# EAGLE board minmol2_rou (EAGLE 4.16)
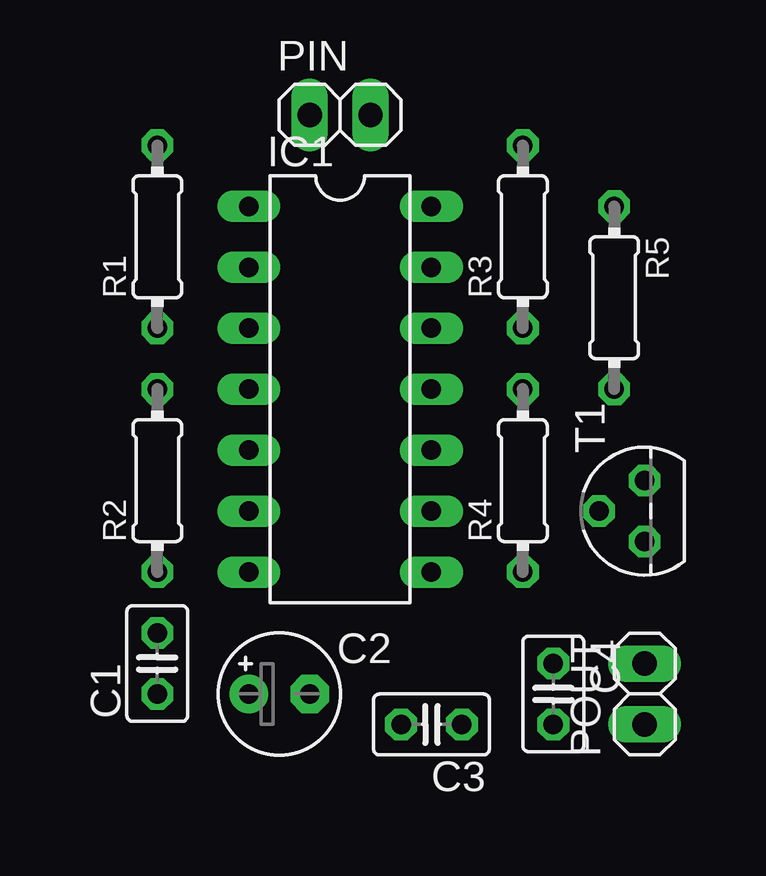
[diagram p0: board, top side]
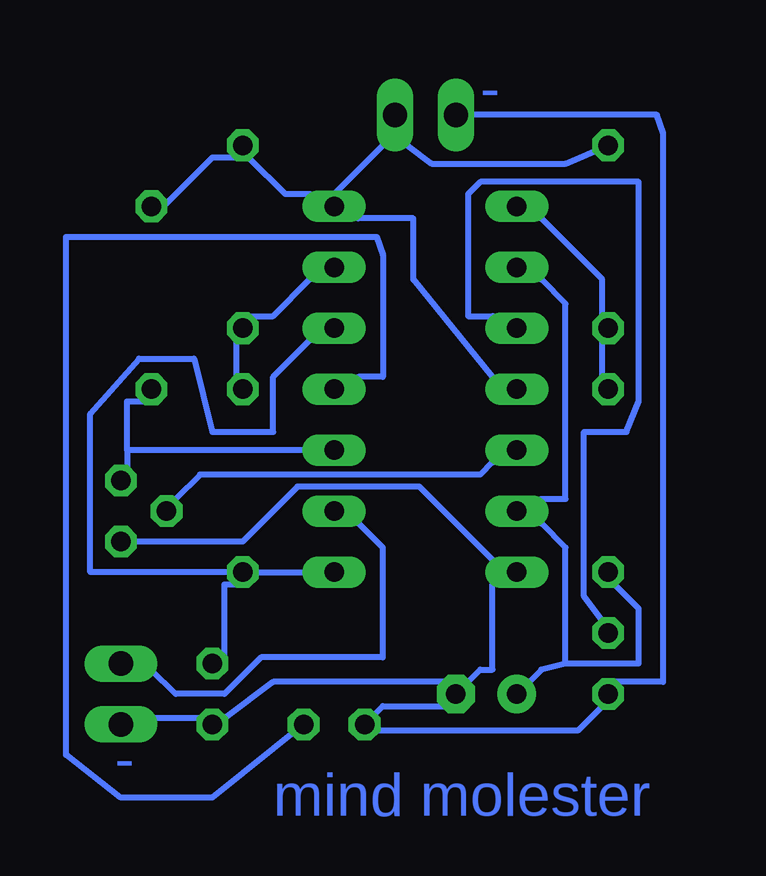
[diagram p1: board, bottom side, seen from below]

No outline drawn. Coordinates in mm, seen from the top.
Copper layers (1*16): Top 0.035mm / dielectric 1.5mm / Bottom 0.035mm
Design rules "default": minimum track width 10mil, minimum drill 24mil, track to track 8mil, track to pad 8mil, pad to pad 8mil, via to via 8mil, smd to smd 8mil, copper to edge 40mil, drill to drill 8mil, minimum pad ring 10mil, minimum via ring 8mil, stop-mask expansion 4mil, vias tented up to drill 0mil, thermal gap 10mil

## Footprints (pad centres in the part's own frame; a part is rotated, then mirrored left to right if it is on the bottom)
C025-025X050 = drill 0.813 octagon: 1 -1.27,0; 2 1.27,0
E2,5-5 = drill 0.813 pad 1.6 round: + -1.27,0 | drill 0.813 pad 1.6 octagon: - 1.27,0
DIL14 = drill 0.813 long: 1 -7.62,-3.81; 2 -5.08,-3.81; 3 -2.54,-3.81; 4 0,-3.81; 5 2.54,-3.81; 6 5.08,-3.81; 7 7.62,-3.81; 8 7.62,3.81; 9 5.08,3.81; 10 2.54,3.81; 11 0,3.81; 12 -2.54,3.81; 13 -5.08,3.81; 14 -7.62,3.81
1X02 = drill 1.016 long: 1 -1.27,0; 2 1.27,0
0204/7 = drill 0.813 octagon: 1 -3.81,0; 2 3.81,0
TO92 = drill 0.813 octagon: 1 -1.27,0; 2 0,1.905; 3 1.27,0

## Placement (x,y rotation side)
C1  100n  [C025-025X050]  21.59,6.35 90 top
C2  20u  [E2,5-5]  26.67,5.08 0 top
C3  100n  [C025-025X050]  33.02,3.81 180 top
C4  1n  [C025-025X050]  38.1,5.08 270 top
IC1  ICL7556  [DIL14]  29.21,17.78 270 top
PIN  [1X02]  29.21,29.21 0 top
POUT  [1X02]  41.91,5.08 90 top
R1  10M  [0204/7]  21.59,24.13 90 top
R2  20k  [0204/7]  21.59,13.97 90 top
R3  33k  [0204/7]  36.83,24.13 90 top
R4  50k  [0204/7]  36.83,13.97 90 top
R5  50k  [0204/7]  40.64,21.59 270 top
T1  2N7000  [TO92]  41.91,12.7 90 top

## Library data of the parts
C1-C4 R1-R5 = rcl
IC1 = 40xx
PIN POUT = pinhead
T1 = linear

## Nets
PIN: IC1.4 IC1.14 PIN.2 R1.2 R3.2 R5.1
POU: C1.1 C2.- C3.2 C4.2 IC1.7 PIN.1 POUT.1 T1.1
S$3: IC1.1 R1.1 R2.2
S$4: IC1.10 R5.2 T1.3
S$5: C1.2 IC1.3
S$6: C2.+ IC1.2 IC1.6 R2.1
S$8: IC1.5 T1.2
S$9: IC1.13 R3.1 R4.2
S$11: C3.1 IC1.11
S$12: C4.1 IC1.8 IC1.12 R4.1
S$13: IC1.9 POUT.2

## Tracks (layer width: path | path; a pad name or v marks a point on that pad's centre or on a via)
PIN
  Bottom 0.254: R1.2 23.37,27.18 28.96,27.18 29.97,27.94 PIN.2 30.99,27.94 33.02,25.91 IC1.14 | IC1.4 26.42,18.29 29.72,22.35 29.72,24.89 32,24.89 IC1.14 | IC1.14 34.04,25.91 35.05,25.91 36.58,27.43 R3.2 37.08,27.43 38.1,27.43 40.13,25.4 R5.1
POU
  Bottom 0.254: POUT.1 40.64,4.06 38.61,4.06 C4.2 37.59,4.06 35.56,5.59 27.94,5.59 C2.- | C2.- 28.45,4.57 30.99,4.57 C3.2 31.5,3.56 22.86,3.56 21.84,4.57 C1.1 21.34,5.59 19.3,5.59 19.3,28.45 19.56,29.21 PIN.1 | C2.- 26.92,6.1 26.42,6.1 26.42,9.65 IC1.7 26.42,10.67 29.46,13.72 34.54,13.72 36.83,11.43 41.4,11.43 41.66,11.68 T1.1
S$3
  Bottom 0.254: R2.2 21.84,18.29 21.84,19.81 R1.1 21.84,20.83 21.84,22.35 24.38,24.89 IC1.1
S$4
  Bottom 0.254: 41.66,15.24 41.66,17.27 40.64,17.27 R5.2 | 41.66,15.24 41.66,14.22 T1.3 | IC1.10 41.66,15.24
S$5
  Bottom 0.254: C1.2 21.84,8.13 22.61,9.14 22.61,16 20.83,16 20.32,17.27 20.32,26.42 26.92,26.42 27.43,25.91 27.43,20.83 26.42,20.83 IC1.3
S$6
  Bottom 0.254: 23.37,6.35 24.38,6.1 C2.+ | 23.37,6.35 20.32,6.35 20.32,8.64 21.34,9.65 R2.1 | 23.37,6.35 23.37,11.18 24.38,12.19 IC1.6 24.38,13.21 23.37,13.21 23.37,21.34 24.38,22.35 IC1.2
S$8
  Bottom 0.254: IC1.5 26.42,14.73 26.92,14.22 38.61,14.22 39.62,13.21 T1.2
S$9
  Bottom 0.254: R4.2 37.08,18.29 37.08,19.81 R3.1 36.58,20.83 35.56,20.83 34.04,22.35 IC1.13
S$11
  Bottom 0.254: C3.1 38.1,0.76 41.91,0.76 44.2,2.54 44.2,24.13 31.24,24.13 30.99,23.37 30.99,18.29 32,18.29 IC1.11
S$12
  Bottom 0.254: C4.1 37.59,6.6 37.59,9.65 37.08,9.65 R4.1 | R4.1 IC1.8 | IC1.12 34.04,19.81 35.56,18.29 35.56,16 38.1,16 38.86,19.05 41.15,19.05 43.18,16.76 43.18,10.16 R4.1
S$13
  Bottom 0.254: IC1.9 32,12.19 30.99,11.18 30.99,6.6 36.07,6.6 37.59,5.08 39.62,5.08 40.64,6.1 POUT.2

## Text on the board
Bottom: - | - | mind molester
